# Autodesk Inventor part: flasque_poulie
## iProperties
Shininess: 64.0
Length Units: 11269
Angle Units: 11279
Time Units: 11290
Mass Units: 11283
Length Display Precision: 3
Angle Display Precision: 2
Compacted: True
Part Number: flasque_poulie
Document SubType Name: Modeling
Created: 2004-05
Material: Par défaut
Designer: David
Density: 0.0
Volumn: 0.0
Area: 0.0
PropertySet Name: Model Information
Control State: 0
Master: False
Checked Out: False
Author: David
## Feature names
1. Révolution1 [Revolution]
